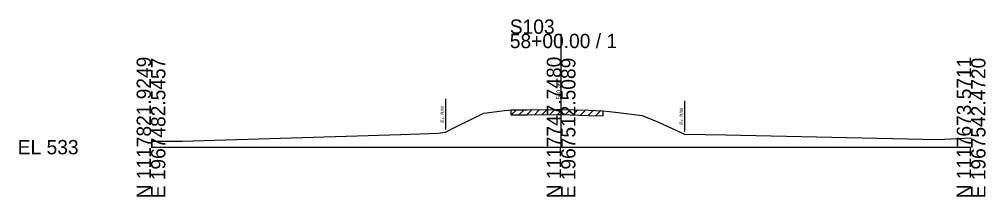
# Model space of a CAD drawing. Extents: x -26 to 163, y -10 to 24018.
# Drawn here: x -25.7 to 162.8, y 7490.3 to 7525 of the extents above; entities that cross this region are included whole.
import ezdxf

# ---------------------------------------------------------------- set-up
doc = ezdxf.new("R2010")
doc.units = 0
for name, color, linetype in [('RD_GPK_XS_Cell', 7, 'Continuous'), ('RD_XS_ExGround', 7, 'Continuous'), ('RD_XS_ExPaveRet', 7, 'Continuous'), ('RD_XS_ExRW', 7, 'Continuous'), ('RD_XS_TX_Elev_EX', 7, 'Continuous')]:
    doc.layers.add(name, color=color, linetype=linetype)

msp = doc.modelspace()

# ---------------------------------------------------------------- linework, layer by layer
at = {"layer": 'RD_GPK_XS_Cell'}
for p, q in [((80, 7500), (80, 7522.17)), ((0, 7500), (80, 7500)), ((80, 7500), (160, 7500))]:
    msp.add_line(p, q, dxfattribs=at)
at = {"layer": 'RD_XS_ExGround'}
msp.add_lwpolyline([(0, 7501.18), (6.09, 7501.15), (48.74, 7502.45), (56.1, 7502.75), (56.89, 7502.87), (57.44, 7502.94), (59.7, 7504.08), (64.9, 7506.66), (68.44, 7507.08), (70.29, 7507.29), (73.36, 7507.32), (79.1, 7507.39), (80, 7507.36), (85.33, 7507.21), (88.17, 7507.13), (90.65, 7506.83), (95.84, 7506.18), (98.98, 7504.87), (104.07, 7502.54), (112.16, 7502.41), (153.5, 7501.5), (160, 7501.84)], dxfattribs=at)
at = {"layer": 'RD_XS_ExPaveRet'}
for p, q in [((77.79, 7506.37), (78.8, 7507.39)), ((70.29, 7506.29), (71.3, 7507.3)), ((70.29, 7506.29), (70.29, 7507.29)), ((70.29, 7506.29), (73.36, 7506.32)), ((71.79, 7506.3), (72.8, 7507.31)), ((73.29, 7506.32), (74.3, 7507.33)), ((73.36, 7506.32), (79.1, 7506.39)), ((74.79, 7506.34), (75.8, 7507.35)), ((76.29, 7506.36), (77.3, 7507.37)), ((79.1, 7506.39), (80, 7506.36)), ((79.29, 7506.38), (80.26, 7507.36)), ((80, 7506.36), (85.33, 7506.21)), ((80.79, 7506.34), (81.76, 7507.31)), ((82.29, 7506.3), (83.26, 7507.27)), ((83.79, 7506.26), (84.76, 7507.23)), ((85.29, 7506.21), (86.26, 7507.19)), ((85.33, 7506.21), (88.17, 7506.13)), ((86.79, 7506.17), (87.76, 7507.14)), ((88.17, 7507.13), (88.17, 7506.13))]:
    msp.add_line(p, q, dxfattribs=at)
at = {"layer": 'RD_XS_ExRW'}
for p, q in [((57.44, 7509.44), (57.44, 7503.44)), ((104.07, 7509.04), (104.07, 7503.04))]:
    msp.add_line(p, q, dxfattribs=at)

# ---------------------------------------------------------------- texts
at = {"layer": 'RD_GPK_XS_Cell'}
for s, p in [('S103', (70, 7522.17)), ('58+00.00 / 1', (70, 7519.37)), ('EL 533', (-26, 7498.6))]:
    msp.add_text(s, height=2.8, dxfattribs=at).set_placement(p)
for s, p in [('N 1117821.9249', (0, 7490)), ('E 1967482.5457', (2.8, 7490)), ('N 1117747.7480', (80, 7490)), ('E 1967512.5089', (82.8, 7490)), ('N 1117673.5711', (160, 7490)), ('E 1967542.4720', (162.8, 7490))]:
    msp.add_text(s, height=2.8, rotation=90, dxfattribs=at).set_placement(p)
at = {"layer": 'RD_XS_ExRW'}
for p in [(57.19, 7504.79), (103.82, 7504.39)]:
    msp.add_text('Ex. R/W ', height=0.65, rotation=90, dxfattribs=at).set_placement(p)
at = {"layer": 'RD_XS_TX_Elev_EX'}
msp.add_text('540.36', height=0.8, rotation=90, dxfattribs=at).set_placement((79.9, 7509.36))

doc.saveas('drawing.dxf')
